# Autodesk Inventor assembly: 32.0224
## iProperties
Created: 2012-10
Part Number: 32.0224
Document SubType Name: Assembly
Designer: Administrator
Description: TOOL TROLLEY
Stock Number: 32.0224 TOOL TROLLEY
Author: Administrator
